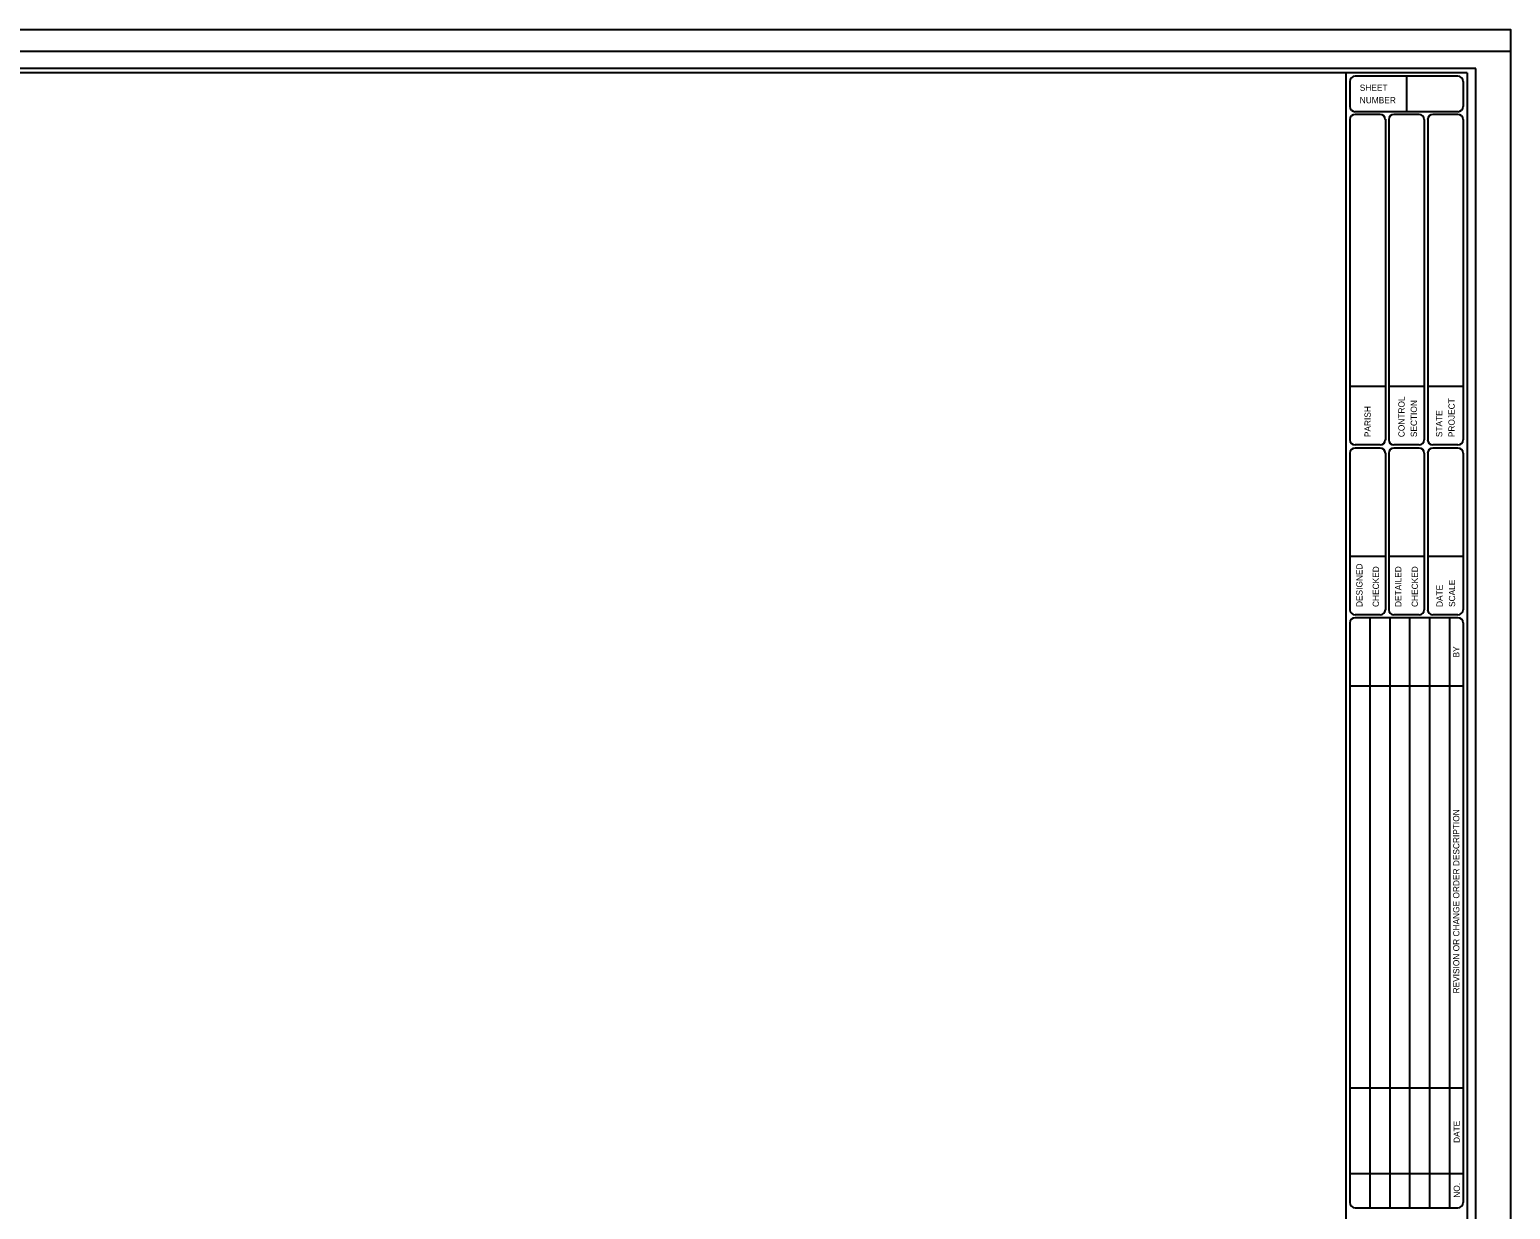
# Model space of a CAD drawing. Extents: x -31.4 to 41.1, y -13.7 to 22.3.
# Drawn here: x -14.27 to 2.83, y 8.4 to 22.04 of the extents above; entities that cross this region are included whole.
import ezdxf

# ---------------------------------------------------------------- set-up
doc = ezdxf.new("R2010")
doc.units = 0
for name, color, linetype in [('Plot Border', 7, 'Continuous'), ('Plot Border 2', 7, 'Continuous'), ('Sheet Border', 7, 'Continuous')]:
    doc.layers.add(name, color=color, linetype=linetype)

msp = doc.modelspace()

# ---------------------------------------------------------------- linework, layer by layer
at = {"layer": 'Plot Border'}
for points in [[(-31.167, 22.04), (2.833, 22.04), (2.833, 0.04), (-31.167, 0.04)], [(2.433, 21.59), (-30.567, 21.59), (-30.567, 0.49), (2.433, 0.49)]]:
    msp.add_lwpolyline(points, close=True, dxfattribs=at)
at = {"layer": 'Plot Border 2'}
msp.add_lwpolyline([(-31.167, 21.79), (2.833, 21.79), (2.833, 0.29), (-31.167, 0.29)], close=True, dxfattribs=at)
at = {"layer": 'Sheet Border'}
for p, q in [((2.333, 21.54), (-29.167, 21.54)), ((0.933, 21.54), (0.933, 0.54)), ((0.98, 21.441), (0.98, 21.15)), ((2.228, 21.5), (1.039, 21.5)), ((1.633, 21.5), (1.633, 21.091)), ((2.287, 21.441), (2.287, 21.15)), ((2.333, 21.54), (2.333, 0.54)), ((2.228, 21.091), (1.039, 21.091)), ((1.329, 21.059), (1.039, 21.059)), ((1.778, 21.059), (1.488, 21.059)), ((2.228, 21.059), (1.937, 21.059)), ((0.98, 21.004), (0.98, 17.294)), ((1.389, 21.004), (1.389, 17.294)), ((1.428, 21), (1.428, 17.299)), ((1.838, 21), (1.838, 17.298)), ((1.878, 21), (1.878, 17.299)), ((2.287, 21), (2.287, 17.299)), ((1.389, 17.913), (0.98, 17.913)), ((1.838, 17.913), (1.428, 17.913)), ((2.287, 17.913), (1.878, 17.913)), ((0.98, 17.147), (0.98, 15.335)), ((1.329, 17.239), (1.039, 17.239)), ((1.33, 17.202), (1.039, 17.202)), ((1.389, 17.143), (1.389, 15.335)), ((1.429, 17.147), (1.429, 15.335)), ((1.778, 17.239), (1.488, 17.239)), ((1.779, 17.202), (1.488, 17.202)), ((1.838, 17.143), (1.838, 15.335)), ((1.878, 17.147), (1.878, 15.335)), ((2.228, 17.239), (1.937, 17.239)), ((2.228, 17.202), (1.937, 17.202)), ((2.288, 17.143), (2.288, 15.335)), ((1.389, 15.949), (0.98, 15.949)), ((1.838, 15.949), (1.428, 15.949)), ((2.287, 15.949), (1.878, 15.949)), ((1.33, 15.276), (1.039, 15.276)), ((2.228, 15.241), (1.039, 15.241)), ((1.209, 15.241), (1.209, 8.422)), ((1.439, 15.241), (1.439, 8.422)), ((1.779, 15.276), (1.488, 15.276)), ((1.669, 15.241), (1.669, 8.422)), ((1.899, 15.241), (1.899, 8.422)), ((2.228, 15.276), (1.937, 15.276)), ((2.129, 15.241), (2.129, 8.422)), ((0.98, 15.182), (0.98, 8.481)), ((2.287, 15.182), (2.287, 8.481)), ((2.287, 14.449), (0.98, 14.449)), ((0.98, 9.808), (2.287, 9.808)), ((0.98, 8.818), (2.287, 8.818)), ((1.039, 8.422), (2.228, 8.422))]:
    msp.add_line(p, q, dxfattribs=at)
for centre, start, end in [((1.039, 21.441), 90, 180), ((2.228, 21.441), 0, 90), ((1.039, 21.15), 180, 270), ((1.039, 21), 90, 180), ((1.329, 21), 0, 90), ((1.488, 21), 90, 180), ((1.778, 21), 0, 90), ((1.937, 21), 90, 180), ((2.228, 21.15), 270, 0), ((2.228, 21), 0, 90), ((1.039, 17.298), 180, 270), ((1.329, 17.298), 270, 0), ((1.488, 17.298), 180, 270), ((1.778, 17.298), 270, 0), ((1.937, 17.298), 180, 270), ((2.228, 17.298), 270, 0), ((1.039, 17.143), 90, 180), ((1.33, 17.143), 0, 90), ((1.488, 17.143), 90, 180), ((1.779, 17.143), 0, 90), ((1.937, 17.143), 90, 180), ((2.228, 17.143), 0, 90), ((1.039, 15.335), 180, 270), ((1.039, 15.182), 90, 180), ((1.33, 15.335), 270, 0), ((1.488, 15.335), 180, 270), ((1.779, 15.335), 270, 0), ((1.937, 15.335), 180, 270), ((2.228, 15.335), 270, 0), ((2.228, 15.182), 0, 90), ((1.039, 8.481), 180, 270), ((2.228, 8.481), 270, 0)]:
    msp.add_arc(centre, 0.0594, start, end, dxfattribs=at)

# ---------------------------------------------------------------- texts
for s, p in [('SHEET', (1.093, 21.332)), ('NUMBER', (1.093, 21.188))]:
    msp.add_text(s, height=0.072, dxfattribs=at).set_placement(p)
for s, p in [('CONTROL', (1.611, 17.329)), ('PARISH', (1.22, 17.329)), ('SECTION', (1.754, 17.329)), ('STATE', (2.046, 17.329)), ('PROJECT', (2.19, 17.329)), ('DESIGNED', (1.125, 15.366)), ('CHECKED', (1.315, 15.366)), ('DETAILED', (1.574, 15.366)), ('CHECKED', (1.765, 15.366)), ('DATE', (2.051, 15.366)), ('SCALE', (2.195, 15.366)), ('BY', (2.244, 14.782)), ('REVISION OR CHANGE ORDER DESCRIPTION', (2.244, 10.899)), ('DATE', (2.249, 9.171)), ('NO.', (2.25, 8.538))]:
    msp.add_text(s, height=0.072, rotation=90, dxfattribs=at).set_placement(p)

doc.saveas('drawing.dxf')
